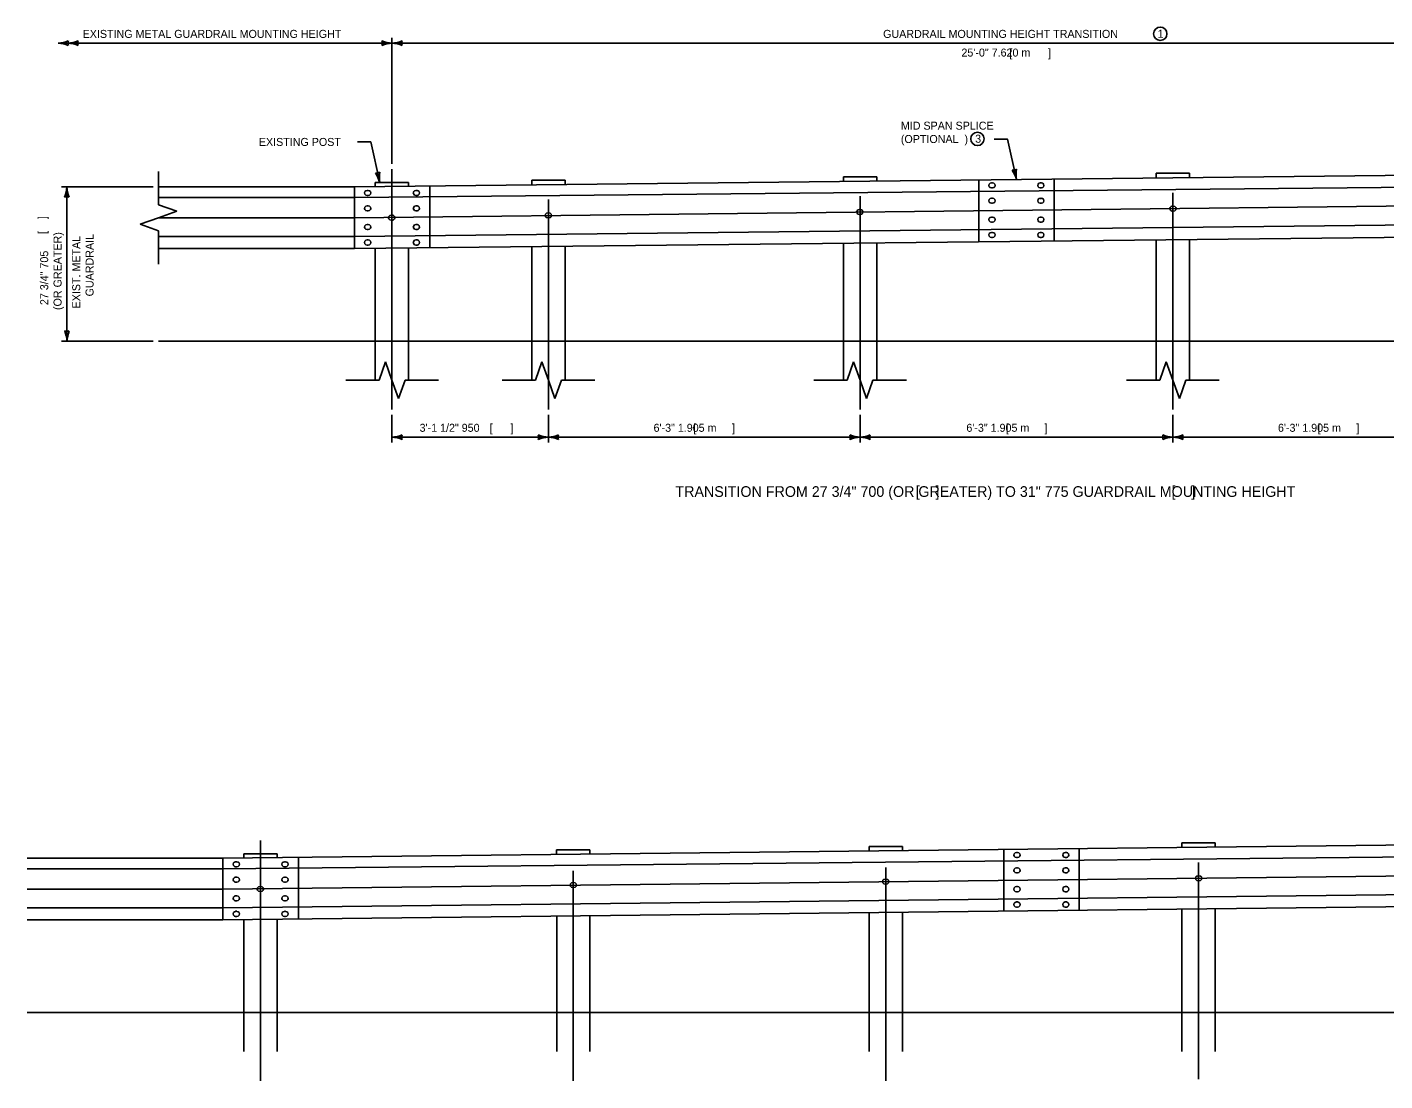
# Model space of a CAD drawing. Extents: x 49991.4 to 50070, y 49987.6 to 50011.4.
# Drawn here: x 50030.61 to 50040.78, y 50001.88 to 50009.78 of the extents above; entities that cross this region are included whole.
import ezdxf

# ---------------------------------------------------------------- set-up
doc = ezdxf.new("R2010")
doc.units = 0
for name, color, linetype in [('Level 1', 7, 'Continuous'), ('Level 2', 7, 'Continuous'), ('Level 3', 7, 'Continuous'), ('Level 4', 7, 'Continuous'), ('Level 5', 7, 'Continuous'), ('Level 6', 7, 'Continuous')]:
    doc.layers.add(name, color=color, linetype=linetype)

msp = doc.modelspace()

# ---------------------------------------------------------------- linework, layer by layer
at = {"layer": 'Level 1'}
for p, q in [((50033.059, 50008.581), (50042.421, 50008.684)), ((50034.389, 50008.595), (50034.389, 50008.631)), ((50034.389, 50008.631), (50034.639, 50008.631)), ((50034.639, 50008.598), (50034.639, 50008.631)), ((50036.725, 50008.657), (50036.725, 50008.621)), ((50036.725, 50008.657), (50036.975, 50008.657)), ((50036.975, 50008.624), (50036.975, 50008.657)), ((50037.74, 50008.633), (50037.74, 50008.17)), ((50039.07, 50008.647), (50039.07, 50008.683)), ((50039.07, 50008.683), (50039.32, 50008.683)), ((50039.32, 50008.65), (50039.32, 50008.683)), ((50031.591, 50008.581), (50033.059, 50008.581)), ((50033.059, 50008.501), (50042.421, 50008.594)), ((50033.059, 50008.581), (50033.059, 50008.491)), ((50033.154, 50008.554), (50033.163, 50008.554)), ((50033.154, 50008.517), (50033.163, 50008.517)), ((50033.216, 50008.614), (50033.216, 50008.582)), ((50033.216, 50008.614), (50033.466, 50008.614)), ((50033.466, 50008.585), (50033.466, 50008.614)), ((50033.52, 50008.554), (50033.529, 50008.554)), ((50033.52, 50008.517), (50033.529, 50008.517)), ((50037.835, 50008.611), (50037.844, 50008.611)), ((50037.835, 50008.573), (50037.844, 50008.573)), ((50038.201, 50008.611), (50038.21, 50008.611)), ((50038.201, 50008.573), (50038.21, 50008.573)), ((50031.591, 50008.501), (50033.059, 50008.501)), ((50033.059, 50008.491), (50033.059, 50008.119)), ((50033.154, 50008.439), (50033.163, 50008.439)), ((50033.52, 50008.439), (50033.529, 50008.439)), ((50036.844, 50008.412), (50036.853, 50008.412)), ((50037.835, 50008.496), (50037.844, 50008.496)), ((50037.835, 50008.458), (50037.844, 50008.458)), ((50038.201, 50008.495), (50038.21, 50008.495)), ((50038.201, 50008.458), (50038.21, 50008.458)), ((50039.191, 50008.437), (50039.2, 50008.437)), ((50033.059, 50008.209), (50042.421, 50008.313)), ((50033.154, 50008.401), (50033.163, 50008.401)), ((50033.335, 50008.369), (50033.344, 50008.369)), ((50033.335, 50008.331), (50033.344, 50008.331)), ((50033.52, 50008.401), (50033.529, 50008.401)), ((50034.509, 50008.386), (50034.518, 50008.386)), ((50034.509, 50008.348), (50034.518, 50008.348)), ((50036.844, 50008.374), (50036.853, 50008.374)), ((50037.835, 50008.355), (50037.844, 50008.355)), ((50037.835, 50008.317), (50037.844, 50008.317)), ((50038.201, 50008.355), (50038.21, 50008.355)), ((50038.201, 50008.317), (50038.21, 50008.317)), ((50039.191, 50008.399), (50039.2, 50008.399)), ((50031.591, 50008.209), (50033.059, 50008.209)), ((50033.059, 50008.119), (50042.702, 50008.223)), ((50033.154, 50008.298), (50033.163, 50008.298)), ((50033.154, 50008.261), (50033.163, 50008.261)), ((50033.52, 50008.298), (50033.529, 50008.298)), ((50033.52, 50008.261), (50033.529, 50008.261)), ((50037.835, 50008.24), (50037.844, 50008.24)), ((50038.201, 50008.239), (50038.21, 50008.239)), ((50031.591, 50008.119), (50033.059, 50008.119)), ((50033.154, 50008.183), (50033.163, 50008.183)), ((50033.154, 50008.145), (50033.163, 50008.145)), ((50033.216, 50007.424), (50033.216, 50008.121)), ((50033.466, 50007.424), (50033.466, 50008.124)), ((50033.52, 50008.183), (50033.529, 50008.183)), ((50033.52, 50008.145), (50033.529, 50008.145)), ((50034.389, 50007.424), (50034.389, 50008.134)), ((50034.639, 50007.424), (50034.639, 50008.136)), ((50036.725, 50007.424), (50036.725, 50008.159)), ((50036.975, 50007.424), (50036.975, 50008.161)), ((50037.835, 50008.202), (50037.844, 50008.202)), ((50038.201, 50008.202), (50038.21, 50008.202)), ((50039.07, 50007.424), (50039.07, 50008.184)), ((50039.32, 50007.424), (50039.32, 50008.187)), ((50031.591, 50007.424), (50033.216, 50007.424)), ((50034.514, 50007.424), (50043.751, 50007.424)), ((50032.074, 50003.548), (50042.608, 50003.665)), ((50036.919, 50003.637), (50036.919, 50003.602)), ((50036.919, 50003.637), (50037.169, 50003.637)), ((50037.169, 50003.604), (50037.169, 50003.637)), ((50039.263, 50003.628), (50039.263, 50003.663)), ((50039.263, 50003.663), (50039.513, 50003.663)), ((50039.513, 50003.63), (50039.513, 50003.663)), ((50030.606, 50003.548), (50032.074, 50003.548)), ((50042.608, 50003.575), (50032.074, 50003.469)), ((50032.074, 50003.548), (50032.074, 50003.458)), ((50032.231, 50003.581), (50032.231, 50003.55)), ((50032.231, 50003.581), (50032.481, 50003.581)), ((50032.481, 50003.552), (50032.481, 50003.581)), ((50034.575, 50003.576), (50034.575, 50003.611)), ((50034.575, 50003.611), (50034.825, 50003.611)), ((50034.825, 50003.578), (50034.825, 50003.611)), ((50037.927, 50003.613), (50037.927, 50003.151)), ((50038.022, 50003.591), (50038.031, 50003.591)), ((50038.022, 50003.553), (50038.031, 50003.553)), ((50038.388, 50003.591), (50038.397, 50003.591)), ((50038.388, 50003.553), (50038.397, 50003.553)), ((50030.606, 50003.469), (50032.074, 50003.469)), ((50032.074, 50003.458), (50032.074, 50003.086)), ((50032.169, 50003.522), (50032.178, 50003.522)), ((50032.169, 50003.484), (50032.178, 50003.484)), ((50032.535, 50003.522), (50032.544, 50003.522)), ((50032.535, 50003.484), (50032.544, 50003.484)), ((50038.022, 50003.476), (50038.031, 50003.476)), ((50038.022, 50003.438), (50038.031, 50003.438)), ((50038.388, 50003.476), (50038.397, 50003.476)), ((50038.388, 50003.438), (50038.397, 50003.438)), ((50032.169, 50003.406), (50032.178, 50003.406)), ((50032.169, 50003.369), (50032.178, 50003.369)), ((50032.35, 50003.336), (50032.359, 50003.336)), ((50032.535, 50003.406), (50032.544, 50003.406)), ((50032.535, 50003.368), (50032.544, 50003.368)), ((50034.696, 50003.366), (50034.705, 50003.366)), ((50034.696, 50003.329), (50034.705, 50003.329)), ((50037.038, 50003.392), (50037.047, 50003.392)), ((50037.038, 50003.355), (50037.047, 50003.355)), ((50038.022, 50003.335), (50038.031, 50003.335)), ((50038.388, 50003.335), (50038.397, 50003.335)), ((50039.384, 50003.417), (50039.393, 50003.417)), ((50039.384, 50003.379), (50039.393, 50003.379)), ((50032.074, 50003.176), (50042.608, 50003.293)), ((50032.169, 50003.266), (50032.178, 50003.266)), ((50032.169, 50003.228), (50032.178, 50003.228)), ((50032.35, 50003.298), (50032.359, 50003.298)), ((50032.535, 50003.266), (50032.544, 50003.266)), ((50032.535, 50003.228), (50032.544, 50003.228)), ((50038.022, 50003.297), (50038.031, 50003.297)), ((50038.388, 50003.297), (50038.397, 50003.297)), ((50030.606, 50003.176), (50032.074, 50003.176)), ((50042.608, 50003.203), (50032.074, 50003.086)), ((50032.169, 50003.15), (50032.178, 50003.15)), ((50032.535, 50003.15), (50032.544, 50003.15)), ((50036.919, 50002.391), (50036.919, 50003.14)), ((50037.169, 50002.391), (50037.169, 50003.143)), ((50038.022, 50003.22), (50038.031, 50003.22)), ((50038.022, 50003.182), (50038.031, 50003.182)), ((50038.388, 50003.22), (50038.397, 50003.22)), ((50038.388, 50003.182), (50038.397, 50003.182)), ((50039.263, 50002.391), (50039.263, 50003.166)), ((50039.513, 50002.391), (50039.513, 50003.169)), ((50030.606, 50003.086), (50032.074, 50003.086)), ((50032.169, 50003.112), (50032.178, 50003.112)), ((50032.231, 50002.391), (50032.231, 50003.088)), ((50032.481, 50002.391), (50032.481, 50003.091)), ((50032.535, 50003.112), (50032.544, 50003.112)), ((50034.576, 50002.391), (50034.576, 50003.114)), ((50034.825, 50002.391), (50034.825, 50003.116)), ((50030.606, 50002.391), (50032.231, 50002.391)), ((50033.529, 50002.391), (50043.938, 50002.391))]:
    msp.add_line(p, q, dxfattribs=at)
for centre, start_param, end_param in [((50033.154, 50008.536), 4.712389, 7.853982), ((50033.163, 50008.536), 1.570796, 4.712389), ((50033.52, 50008.536), 4.712389, 7.853982), ((50033.529, 50008.536), 1.570796, 4.712389), ((50037.835, 50008.592), 4.712389, 7.853982), ((50037.844, 50008.592), 1.570796, 4.712389), ((50038.201, 50008.592), 4.712389, 7.853982), ((50038.21, 50008.592), 1.570796, 4.712389), ((50033.154, 50008.42), 4.712389, 7.853982), ((50033.163, 50008.42), 1.570796, 4.712389), ((50033.52, 50008.42), 4.712389, 7.853982), ((50033.529, 50008.42), 1.570796, 4.712389), ((50036.844, 50008.393), 4.712389, 7.853982), ((50036.853, 50008.393), 1.570796, 4.712389), ((50037.835, 50008.477), 4.712389, 7.853982), ((50037.844, 50008.477), 1.570796, 4.712389), ((50038.201, 50008.477), 4.712389, 7.853982), ((50038.21, 50008.477), 1.570796, 4.712389), ((50039.191, 50008.418), 4.712389, 7.853982), ((50039.2, 50008.418), 1.570796, 4.712389), ((50033.335, 50008.35), 4.712389, 7.853982), ((50033.344, 50008.35), 1.570796, 4.712389), ((50034.509, 50008.367), 4.712389, 7.853982), ((50034.518, 50008.367), 1.570796, 4.712389), ((50037.835, 50008.336), 4.712389, 7.853982), ((50037.844, 50008.336), 1.570796, 4.712389), ((50038.201, 50008.336), 4.712389, 7.853982), ((50038.21, 50008.336), 1.570796, 4.712389), ((50033.154, 50008.28), 4.712389, 7.853982), ((50033.163, 50008.28), 1.570796, 4.712389), ((50033.52, 50008.28), 4.712389, 7.853982), ((50033.529, 50008.28), 1.570796, 4.712389), ((50037.835, 50008.221), 4.712389, 7.853982), ((50037.844, 50008.221), 1.570796, 4.712389), ((50038.201, 50008.221), 4.712389, 7.853982), ((50038.21, 50008.221), 1.570796, 4.712389), ((50033.154, 50008.164), 4.712389, 7.853982), ((50033.163, 50008.164), 1.570796, 4.712389), ((50033.52, 50008.164), 4.712389, 7.853982), ((50033.529, 50008.164), 1.570796, 4.712389), ((50038.022, 50003.572), 4.712389, 7.853982), ((50038.031, 50003.572), 1.570796, 4.712389), ((50038.388, 50003.572), 4.712389, 7.853982), ((50038.397, 50003.572), 1.570796, 4.712389), ((50032.169, 50003.503), 4.712389, 7.853982), ((50032.178, 50003.503), 1.570796, 4.712389), ((50032.535, 50003.503), 4.712389, 7.853982), ((50032.544, 50003.503), 1.570796, 4.712389), ((50038.022, 50003.457), 4.712389, 7.853982), ((50038.031, 50003.457), 1.570796, 4.712389), ((50038.388, 50003.457), 4.712389, 7.853982), ((50038.397, 50003.457), 1.570796, 4.712389), ((50032.169, 50003.387), 4.712389, 7.853982), ((50032.178, 50003.387), 1.570796, 4.712389), ((50032.35, 50003.317), 4.712389, 7.853982), ((50032.359, 50003.317), 1.570796, 4.712389), ((50032.535, 50003.387), 4.712389, 7.853982), ((50032.544, 50003.387), 1.570796, 4.712389), ((50034.696, 50003.347), 4.712389, 7.853982), ((50034.705, 50003.347), 1.570796, 4.712389), ((50037.038, 50003.373), 4.712389, 7.853982), ((50037.047, 50003.373), 1.570796, 4.712389), ((50038.022, 50003.316), 4.712389, 7.853982), ((50038.031, 50003.316), 1.570796, 4.712389), ((50038.388, 50003.316), 4.712389, 7.853982), ((50038.397, 50003.316), 1.570796, 4.712389), ((50039.384, 50003.398), 4.712389, 7.853982), ((50039.393, 50003.398), 1.570796, 4.712389), ((50032.169, 50003.247), 4.712389, 7.853982), ((50032.178, 50003.247), 1.570796, 4.712389), ((50032.535, 50003.247), 4.712389, 7.853982), ((50032.544, 50003.247), 1.570796, 4.712389), ((50032.169, 50003.131), 4.712389, 7.853982), ((50032.178, 50003.131), 1.570796, 4.712389), ((50032.535, 50003.131), 4.712389, 7.853982), ((50032.544, 50003.131), 1.570796, 4.712389), ((50038.022, 50003.201), 4.712389, 7.853982), ((50038.031, 50003.201), 1.570796, 4.712389), ((50038.388, 50003.201), 4.712389, 7.853982), ((50038.397, 50003.201), 1.570796, 4.712389)]:
    msp.add_ellipse(centre, major_axis=(-0.0189, 0), ratio=0.998676, start_param=start_param, end_param=end_param, dxfattribs=at)
at = {"layer": 'Level 2'}
for p, q in [((50033.216, 50007.424), (50034.514, 50007.424)), ((50032.231, 50002.391), (50033.529, 50002.391))]:
    msp.add_line(p, q, dxfattribs=at)
for centre in [(50039.101, 50009.729), (50037.73, 50008.941)]:
    msp.add_circle(centre, 0.05, dxfattribs=at)
at = {"layer": 'Level 3'}
for p, q in [((50030.839, 50009.658), (50033.341, 50009.658)), ((50033.341, 50008.754), (50033.341, 50009.698)), ((50042.704, 50009.658), (50033.341, 50009.658)), ((50031.551, 50008.581), (50030.864, 50008.581)), ((50030.904, 50008.581), (50030.904, 50007.424)), ((50031.551, 50007.424), (50030.864, 50007.424)), ((50033.341, 50006.665), (50033.341, 50006.872)), ((50034.514, 50006.665), (50034.514, 50006.872)), ((50036.85, 50006.665), (50036.85, 50006.872)), ((50039.195, 50006.665), (50039.195, 50006.872)), ((50033.341, 50006.705), (50034.514, 50006.705)), ((50034.514, 50006.705), (50036.85, 50006.705)), ((50036.85, 50006.705), (50039.195, 50006.705)), ((50039.195, 50006.705), (50041.531, 50006.705))]:
    msp.add_line(p, q, dxfattribs=at)
for points in [[(50038.023, 50008.636), (50037.955, 50008.94), (50037.855, 50008.94)], [(50033.25, 50008.614), (50033.182, 50008.918), (50033.082, 50008.918)]]:
    msp.add_lwpolyline(points, dxfattribs=at)
for centre, radius, start, end in [((50030.829, 50009.88), 0.222, 272.3605, 292.544), ((50030.827, 50009.425), 0.233, 67.9228, 87.1727), ((50030.967, 50009.658), 0.0548, 162.1388, 197.8612), ((50030.903, 50009.88), 0.222, 272.3605, 292.544), ((50030.901, 50009.425), 0.233, 67.9228, 87.1727), ((50031.04, 50009.658), 0.0548, 162.1388, 197.8612), ((50033.351, 50009.88), 0.222, 247.456, 267.6395), ((50033.213, 50009.658), 0.0548, 342.1388, 17.8612), ((50033.353, 50009.425), 0.233, 92.8273, 112.0772), ((50033.33, 50009.891), 0.233, 272.8273, 292.0772), ((50033.332, 50009.436), 0.222, 67.456, 87.6395), ((50033.47, 50009.658), 0.0548, 162.1388, 197.8612), ((50033.222, 50008.739), 0.0548, 264.6827, 300.405), ((50033.025, 50008.552), 0.233, 15.3711, 34.621), ((50033.469, 50008.653), 0.222, 169.9998, 190.1834), ((50037.995, 50008.761), 0.0548, 264.6827, 300.405), ((50037.995, 50008.761), 0.0548, 264.6827, 300.405), ((50037.798, 50008.574), 0.233, 15.3711, 34.621), ((50037.798, 50008.574), 0.233, 15.3711, 34.621), ((50038.242, 50008.675), 0.222, 169.9998, 190.1834), ((50038.242, 50008.675), 0.222, 169.9998, 190.1834), ((50030.682, 50008.59), 0.222, 337.456, 357.6395), ((50031.137, 50008.592), 0.233, 182.8273, 202.0772), ((50030.904, 50008.452), 0.0548, 72.1388, 107.8612), ((50030.904, 50007.553), 0.0548, 252.1388, 287.8612), ((50030.672, 50007.413), 0.233, 2.8273, 22.0772), ((50030.904, 50007.553), 0.0548, 252.1388, 287.8612), ((50030.672, 50007.413), 0.233, 2.8273, 22.0772), ((50031.127, 50007.415), 0.222, 157.456, 177.6395), ((50031.127, 50007.415), 0.222, 157.456, 177.6395), ((50033.33, 50006.937), 0.233, 272.8273, 292.0772), ((50033.33, 50006.937), 0.233, 272.8273, 292.0772), ((50033.332, 50006.483), 0.222, 67.456, 87.6395), ((50033.332, 50006.483), 0.222, 67.456, 87.6395), ((50033.47, 50006.705), 0.0548, 162.1388, 197.8612), ((50033.47, 50006.705), 0.0548, 162.1388, 197.8612), ((50034.523, 50006.927), 0.222, 247.456, 267.6395), ((50034.386, 50006.705), 0.0548, 342.1388, 17.8612), ((50034.523, 50006.927), 0.222, 247.456, 267.6395), ((50034.386, 50006.705), 0.0548, 342.1388, 17.8612), ((50034.525, 50006.472), 0.233, 92.8273, 112.0772), ((50034.525, 50006.472), 0.233, 92.8273, 112.0772), ((50034.503, 50006.937), 0.233, 272.8273, 292.0772), ((50034.503, 50006.937), 0.233, 272.8273, 292.0772), ((50034.505, 50006.483), 0.222, 67.456, 87.6395), ((50034.505, 50006.483), 0.222, 67.456, 87.6395), ((50034.642, 50006.705), 0.0548, 162.1388, 197.8612), ((50034.642, 50006.705), 0.0548, 162.1388, 197.8612), ((50036.859, 50006.927), 0.222, 247.456, 267.6395), ((50036.722, 50006.705), 0.0548, 342.1388, 17.8612), ((50036.859, 50006.927), 0.222, 247.456, 267.6395), ((50036.722, 50006.705), 0.0548, 342.1388, 17.8612), ((50036.862, 50006.472), 0.233, 92.8273, 112.0772), ((50036.862, 50006.472), 0.233, 92.8273, 112.0772), ((50036.839, 50006.937), 0.233, 272.8273, 292.0772), ((50036.839, 50006.937), 0.233, 272.8273, 292.0772), ((50036.841, 50006.483), 0.222, 67.456, 87.6395), ((50036.841, 50006.483), 0.222, 67.456, 87.6395), ((50036.978, 50006.705), 0.0548, 162.1388, 197.8612), ((50036.978, 50006.705), 0.0548, 162.1388, 197.8612), ((50039.204, 50006.927), 0.222, 247.456, 267.6395), ((50039.067, 50006.705), 0.0548, 342.1388, 17.8612), ((50039.204, 50006.927), 0.222, 247.456, 267.6395), ((50039.067, 50006.705), 0.0548, 342.1388, 17.8612), ((50039.207, 50006.472), 0.233, 92.8273, 112.0772), ((50039.207, 50006.472), 0.233, 92.8273, 112.0772), ((50039.184, 50006.937), 0.233, 272.8273, 292.0772), ((50039.184, 50006.937), 0.233, 272.8273, 292.0772), ((50039.186, 50006.483), 0.222, 67.456, 87.6395), ((50039.186, 50006.483), 0.222, 67.456, 87.6395), ((50039.323, 50006.705), 0.0548, 162.1388, 197.8612), ((50039.323, 50006.705), 0.0548, 162.1388, 197.8612)]:
    msp.add_arc(centre, radius, start, end, dxfattribs=at)
at = {"layer": 'Level 4'}
for p, q in [((50038.306, 50008.639), (50038.306, 50008.176)), ((50033.624, 50008.587), (50033.624, 50008.125)), ((50033.216, 50007.424), (50033.216, 50007.131)), ((50033.466, 50007.424), (50033.466, 50007.131)), ((50034.389, 50007.424), (50034.389, 50007.131)), ((50034.639, 50007.424), (50034.639, 50007.131)), ((50036.725, 50007.424), (50036.725, 50007.131)), ((50036.975, 50007.424), (50036.975, 50007.131)), ((50039.07, 50007.424), (50039.07, 50007.131)), ((50039.32, 50007.424), (50039.32, 50007.131)), ((50032.64, 50003.554), (50032.64, 50003.092)), ((50038.493, 50003.619), (50038.493, 50003.158)), ((50032.231, 50002.391), (50032.231, 50002.098)), ((50032.481, 50002.391), (50032.481, 50002.098)), ((50034.576, 50002.391), (50034.576, 50002.098)), ((50034.825, 50002.391), (50034.825, 50002.098)), ((50036.919, 50002.391), (50036.919, 50002.098)), ((50037.169, 50002.391), (50037.169, 50002.098)), ((50039.263, 50002.391), (50039.263, 50002.098)), ((50039.513, 50002.391), (50039.513, 50002.098))]:
    msp.add_line(p, q, dxfattribs=at)
at = {"layer": 'Level 5'}
for p, q in [((50033.341, 50008.714), (50033.341, 50006.912)), ((50039.195, 50008.537), (50039.195, 50006.912)), ((50042.421, 50008.454), (50033.059, 50008.35)), ((50034.514, 50008.486), (50034.514, 50006.912)), ((50036.85, 50008.512), (50036.85, 50006.912)), ((50033.059, 50008.35), (50031.591, 50008.35)), ((50032.356, 50003.681), (50032.356, 50001.879)), ((50032.074, 50003.317), (50042.608, 50003.434)), ((50034.7, 50003.453), (50034.7, 50001.879)), ((50037.044, 50003.479), (50037.044, 50001.879)), ((50039.388, 50003.517), (50039.388, 50001.892)), ((50032.074, 50003.317), (50030.606, 50003.317))]:
    msp.add_line(p, q, dxfattribs=at)
at = {"layer": 'Level 6'}
for p, q in [((50031.591, 50008.697), (50031.591, 50008.447)), ((50031.728, 50008.398), (50031.591, 50008.447)), ((50031.591, 50008.35), (50031.454, 50008.301)), ((50031.728, 50008.398), (50031.591, 50008.35)), ((50031.591, 50008.252), (50031.454, 50008.301)), ((50031.591, 50008.252), (50031.591, 50008.002)), ((50033.293, 50007.269), (50033.244, 50007.131)), ((50033.293, 50007.269), (50033.341, 50007.131)), ((50034.465, 50007.269), (50034.417, 50007.131)), ((50034.465, 50007.269), (50034.514, 50007.131)), ((50036.801, 50007.269), (50036.753, 50007.131)), ((50036.801, 50007.269), (50036.85, 50007.131)), ((50039.146, 50007.269), (50039.098, 50007.131)), ((50039.146, 50007.269), (50039.195, 50007.131)), ((50032.994, 50007.131), (50033.244, 50007.131)), ((50033.341, 50007.131), (50033.39, 50006.994)), ((50033.439, 50007.131), (50033.39, 50006.994)), ((50033.439, 50007.131), (50033.689, 50007.131)), ((50034.167, 50007.131), (50034.417, 50007.131)), ((50034.514, 50007.131), (50034.562, 50006.994)), ((50034.611, 50007.131), (50034.562, 50006.994)), ((50034.611, 50007.131), (50034.861, 50007.131)), ((50036.503, 50007.131), (50036.753, 50007.131)), ((50036.85, 50007.131), (50036.899, 50006.994)), ((50036.947, 50007.131), (50036.899, 50006.994)), ((50036.947, 50007.131), (50037.197, 50007.131)), ((50038.848, 50007.131), (50039.098, 50007.131)), ((50039.195, 50007.131), (50039.244, 50006.994)), ((50039.292, 50007.131), (50039.244, 50006.994)), ((50039.292, 50007.131), (50039.542, 50007.131))]:
    msp.add_line(p, q, dxfattribs=at)

# ---------------------------------------------------------------- texts
at = {"layer": 'Level 2'}
for s, height, p in [('EXISTING METAL GUARDRAIL MOUNTING HEIGHT', 0.06, (50031.022, 50009.698)), ('GUARDRAIL MOUNTING HEIGHT TRANSITION', 0.06, (50037.023, 50009.698)), ('1', 0.06, (50039.081, 50009.699)), ('25\'-0" 7.620 m', 0.06, (50037.61, 50009.558)), ('[            ]', 0.06, (50037.969, 50009.556)), ('MID SPAN SPLICE', 0.06, (50037.156, 50009.01)), ('EXISTING POST', 0.06, (50032.343, 50008.888)), ('(OPTIONAL  )', 0.06, (50037.156, 50008.91)), ('3', 0.06, (50037.713, 50008.912)), ('3\'-1 1/2" 950', 0.06, (50033.548, 50006.745)), ('[      ]', 0.06, (50034.073, 50006.744)), ('6\'-3" 1.905 m', 0.06, (50035.302, 50006.745)), ('[            ]', 0.06, (50035.6, 50006.744)), ('6\'-3" 1.905 m', 0.06, (50037.647, 50006.745)), ('[            ]', 0.06, (50037.943, 50006.744)), ('6\'-3" 1.905 m', 0.06, (50039.983, 50006.745)), ('[            ]', 0.06, (50040.281, 50006.744)), ('TRANSITION FROM 27 3/4" 700 (OR GREATER) TO 31" 775 GUARDRAIL MOUNTING HEIGHT', 0.08, (50035.466, 50006.257)), ('[    ]', 0.08, (50037.267, 50006.26)), ('[    ]', 0.08, (50039.185, 50006.26))]:
    msp.add_text(s, height=height, dxfattribs=at).set_placement(p)
for s, rotation, p in [('[    ]', 270, (50030.703, 50008.362)), ('(OR GREATER)', 90, (50030.864, 50007.658)), ('EXIST. METAL', 90, (50031.004, 50007.67)), ('GUARDRAIL', 90, (50031.104, 50007.76)), ('27 3/4" 705 ', 90, (50030.764, 50007.695))]:
    msp.add_text(s, height=0.06, rotation=rotation, dxfattribs=at).set_placement(p)

doc.saveas('drawing.dxf')
